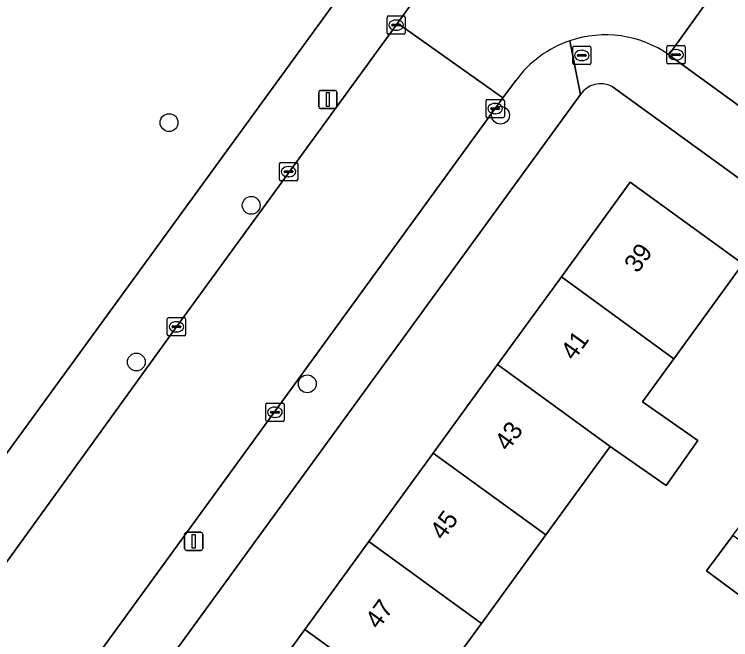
# Model space of a CAD drawing. Extents: x 159674 to 160531, y 382172 to 382904.
# Drawn here: x 160100.56 to 160139.82, y 382591.51 to 382625.81 of the extents above; entities that cross this region are included whole.
import ezdxf

# ---------------------------------------------------------------- set-up
doc = ezdxf.new("R2010")
doc.units = 0
for name, color, linetype in [('IMGEO_Boom', 7, 'Continuous'), ('IMGEO_Brandkraan', 7, 'Continuous'), ('IMGEO_Erf', 7, 'Continuous'), ('IMGEO_Kolk', 7, 'Continuous'), ('IMGEO_Lichtmast', 7, 'Continuous'), ('IMGEO_Pand', 7, 'Continuous'), ('IMGEO_Pand_nummerreeks', 7, 'Continuous'), ('IMGEO_Rijbaan_lokaal_open', 7, 'Continuous'), ('IMGEO_Voetpad_open', 7, 'Continuous')]:
    doc.layers.add(name, color=color, linetype=linetype)

msp = doc.modelspace()

# ---------------------------------------------------------------- linework, layer by layer
at = {"layer": 'IMGEO_Boom'}
for centre in [(160127.205, 382620.272), (160109.04, 382619.867), (160113.544, 382615.329), (160107.245, 382606.738), (160116.616, 382605.543)]:
    msp.add_circle(centre, 0.489, dxfattribs=at)
at = {"layer": 'IMGEO_Brandkraan'}
for p, q in [((160131.163, 382623.125), (160131.163, 382623.977)), ((160131.238, 382624.051), (160132.09, 382624.051)), ((160131.651, 382623.831), (160131.676, 382623.831)), ((160132.164, 382623.977), (160132.164, 382623.125)), ((160131.422, 382623.545), (160131.422, 382623.557)), ((160131.86, 382623.508), (160131.462, 382623.508)), ((160131.465, 382623.594), (160131.863, 382623.594)), ((160131.906, 382623.557), (160131.906, 382623.545)), ((160132.09, 382623.051), (160131.238, 382623.051)), ((160131.674, 382623.271), (160131.649, 382623.271))]:
    msp.add_line(p, q, dxfattribs=at)
for points in [[(160131.163, 382623.125), (160131.163, 382623.977)], [(160131.238, 382624.051), (160132.09, 382624.051)], [(160132.164, 382623.977), (160132.164, 382623.125)], [(160132.09, 382623.051), (160131.238, 382623.051)]]:
    msp.add_lwpolyline(points, dxfattribs=at)
for centre, radius, start, end in [((160131.24, 382623.975), 0.0765, 91.552, 178.448), ((160131.24, 382623.975), 0.0765, 91.552, 178.448), ((160132.088, 382623.975), 0.0765, 1.552, 88.448), ((160132.088, 382623.975), 0.0765, 1.552, 88.448), ((160131.462, 382623.554), 0.0403, 85.8775, 175.7526), ((160131.459, 382623.544), 0.0366, 178.938, 274.7102), ((160131.863, 382623.551), 0.043, 264.8664, 352.4533), ((160131.867, 382623.556), 0.0386, 1.7309, 96.639), ((160131.24, 382623.127), 0.0765, 181.552, 268.448), ((160131.24, 382623.127), 0.0765, 181.552, 268.448), ((160132.088, 382623.127), 0.0765, 271.552, 358.448), ((160132.088, 382623.127), 0.0765, 271.552, 358.448)]:
    msp.add_arc(centre, radius, start, end, dxfattribs=at)
for centre, major_axis, ratio, start_param, end_param in [((160131.65, 382623.551), (-0.387, 0.002), 0.722429, 4.712389, 7.853982), ((160131.675, 382623.551), (-0.39, 0.002), 0.717154, 1.570796, 4.712389)]:
    msp.add_ellipse(centre, major_axis=major_axis, ratio=ratio, start_param=start_param, end_param=end_param, dxfattribs=at)
at = {"layer": 'IMGEO_Erf'}
for points in [[(160078.977, 382572.654), (160139.025, 382655.211), (160118.682, 382670.24), (160112.498, 382662.82), (160085.741, 382648.366)], [(160143.206, 382591.48), (160143.351, 382591.675), (160138.506, 382595.279), (160139.948, 382597.218), (160141.485, 382599.284), (160142.407, 382598.663), (160144.535, 382601.523), (160148.493, 382598.578), (160150.775, 382601.469), (160145.778, 382605.101), (160147.195, 382607.051), (160152.192, 382603.418), (160154.437, 382606.506), (160154.426, 382606.548), (160133.33, 382621.844)], [(160131.588, 382621.403), (160103.888, 382583.337)]]:
    msp.add_lwpolyline(points, dxfattribs=at)
msp.add_lwpolyline([(160133.217, 382602.109), (160129.69, 382597.257), (160126.162, 382592.404), (160124.357, 382589.921), (160126.478, 382588.471), (160124.848, 382586.086), (160122.658, 382587.583), (160125.105, 382585.804), (160121.543, 382580.904), (160119.095, 382582.683), (160115.643, 382577.934), (160109.474, 382582.419), (160112.925, 382587.167), (160116.488, 382592.067), (160119.993, 382596.889), (160123.52, 382601.741), (160127.047, 382606.593), (160130.542, 382611.402), (160134.322, 382616.601), (160140.492, 382612.116), (160136.713, 382606.917), (160134.991, 382604.549), (160138.019, 382602.434), (160136.291, 382599.961)], close=True, dxfattribs=at)
msp.add_arc((160132.7, 382620.672), 1.33, 61.7224, 146.6903, dxfattribs=at)
at = {"layer": 'IMGEO_Kolk'}
for p, q in [((160121.062, 382625.714), (160121.914, 382625.714)), ((160120.987, 382624.788), (160120.987, 382625.64)), ((160121.475, 382625.494), (160121.5, 382625.494)), ((160121.988, 382625.64), (160121.988, 382624.788)), ((160121.246, 382625.208), (160121.246, 382625.22)), ((160121.684, 382625.171), (160121.286, 382625.171)), ((160121.289, 382625.257), (160121.687, 382625.257)), ((160121.498, 382624.934), (160121.473, 382624.934)), ((160121.73, 382625.22), (160121.73, 382625.208)), ((160121.914, 382624.714), (160121.062, 382624.714)), ((160136.327, 382623.163), (160136.327, 382624.015)), ((160136.402, 382624.089), (160137.254, 382624.089)), ((160136.815, 382623.869), (160136.84, 382623.869)), ((160137.328, 382624.015), (160137.328, 382623.163)), ((160136.586, 382623.583), (160136.586, 382623.595)), ((160137.024, 382623.546), (160136.626, 382623.546)), ((160136.629, 382623.632), (160137.027, 382623.632)), ((160137.07, 382623.595), (160137.07, 382623.583)), ((160137.254, 382623.089), (160136.402, 382623.089)), ((160136.838, 382623.309), (160136.813, 382623.309)), ((160126.417, 382620.21), (160126.417, 382621.062)), ((160126.492, 382621.136), (160127.344, 382621.136)), ((160127.418, 382621.062), (160127.418, 382620.21)), ((160126.676, 382620.63), (160126.676, 382620.642)), ((160126.719, 382620.679), (160127.117, 382620.679)), ((160126.905, 382620.916), (160126.93, 382620.916)), ((160127.16, 382620.642), (160127.16, 382620.63)), ((160127.114, 382620.593), (160126.716, 382620.593)), ((160126.928, 382620.356), (160126.903, 382620.356)), ((160127.344, 382620.136), (160126.492, 382620.136)), ((160115.09, 382616.749), (160115.09, 382617.601)), ((160115.165, 382617.675), (160116.017, 382617.675)), ((160116.091, 382617.601), (160116.091, 382616.749)), ((160115.349, 382617.169), (160115.349, 382617.181)), ((160115.787, 382617.132), (160115.389, 382617.132)), ((160115.392, 382617.218), (160115.79, 382617.218)), ((160115.578, 382617.455), (160115.603, 382617.455)), ((160115.833, 382617.181), (160115.833, 382617.169)), ((160116.017, 382616.675), (160115.165, 382616.675)), ((160115.601, 382616.895), (160115.576, 382616.895)), ((160108.942, 382608.244), (160108.942, 382609.096)), ((160109.017, 382609.17), (160109.869, 382609.17)), ((160109.43, 382608.95), (160109.455, 382608.95)), ((160109.943, 382609.096), (160109.943, 382608.244)), ((160109.201, 382608.664), (160109.201, 382608.676)), ((160109.639, 382608.627), (160109.241, 382608.627)), ((160109.244, 382608.713), (160109.642, 382608.713)), ((160109.685, 382608.676), (160109.685, 382608.664)), ((160109.869, 382608.17), (160109.017, 382608.17)), ((160109.453, 382608.39), (160109.428, 382608.39)), ((160114.343, 382603.556), (160114.343, 382604.408)), ((160114.418, 382604.482), (160115.27, 382604.482)), ((160114.831, 382604.262), (160114.856, 382604.262)), ((160115.344, 382604.408), (160115.344, 382603.556)), ((160114.602, 382603.976), (160114.602, 382603.988)), ((160115.04, 382603.939), (160114.642, 382603.939)), ((160114.645, 382604.025), (160115.043, 382604.025)), ((160115.086, 382603.988), (160115.086, 382603.976)), ((160115.27, 382603.482), (160114.418, 382603.482)), ((160114.854, 382603.702), (160114.829, 382603.702))]:
    msp.add_line(p, q, dxfattribs=at)
for points in [[(160121.062, 382625.714), (160121.914, 382625.714)], [(160120.987, 382624.788), (160120.987, 382625.64)], [(160121.988, 382625.64), (160121.988, 382624.788)], [(160121.914, 382624.714), (160121.062, 382624.714)], [(160136.327, 382623.163), (160136.327, 382624.015)], [(160136.402, 382624.089), (160137.254, 382624.089)], [(160137.328, 382624.015), (160137.328, 382623.163)], [(160137.254, 382623.089), (160136.402, 382623.089)], [(160126.417, 382620.21), (160126.417, 382621.062)], [(160126.492, 382621.136), (160127.344, 382621.136)], [(160127.418, 382621.062), (160127.418, 382620.21)], [(160127.344, 382620.136), (160126.492, 382620.136)], [(160115.09, 382616.749), (160115.09, 382617.601)], [(160115.165, 382617.675), (160116.017, 382617.675)], [(160116.091, 382617.601), (160116.091, 382616.749)], [(160116.017, 382616.675), (160115.165, 382616.675)], [(160108.942, 382608.244), (160108.942, 382609.096)], [(160109.017, 382609.17), (160109.869, 382609.17)], [(160109.943, 382609.096), (160109.943, 382608.244)], [(160109.869, 382608.17), (160109.017, 382608.17)], [(160114.343, 382603.556), (160114.343, 382604.408)], [(160114.418, 382604.482), (160115.27, 382604.482)], [(160115.344, 382604.408), (160115.344, 382603.556)], [(160115.27, 382603.482), (160114.418, 382603.482)]]:
    msp.add_lwpolyline(points, dxfattribs=at)
for centre, radius, start, end in [((160121.064, 382625.638), 0.0765, 91.552, 178.448), ((160121.064, 382625.638), 0.0765, 91.552, 178.448), ((160121.912, 382625.638), 0.0765, 1.552, 88.448), ((160121.912, 382625.638), 0.0765, 1.552, 88.448), ((160121.286, 382625.217), 0.0403, 85.8775, 175.7526), ((160121.283, 382625.207), 0.0366, 178.938, 274.7102), ((160121.687, 382625.214), 0.043, 264.8664, 352.4533), ((160121.691, 382625.219), 0.0386, 1.7309, 96.639), ((160121.064, 382624.79), 0.0765, 181.552, 268.448), ((160121.064, 382624.79), 0.0765, 181.552, 268.448), ((160121.912, 382624.79), 0.0765, 271.552, 358.448), ((160121.912, 382624.79), 0.0765, 271.552, 358.448), ((160136.404, 382624.013), 0.0765, 91.552, 178.448), ((160136.404, 382624.013), 0.0765, 91.552, 178.448), ((160137.252, 382624.013), 0.0765, 1.552, 88.448), ((160137.252, 382624.013), 0.0765, 1.552, 88.448), ((160136.626, 382623.592), 0.0403, 85.8775, 175.7526), ((160136.623, 382623.582), 0.0366, 178.938, 274.7102), ((160137.027, 382623.589), 0.043, 264.8664, 352.4533), ((160137.031, 382623.594), 0.0386, 1.7309, 96.639), ((160136.404, 382623.165), 0.0765, 181.552, 268.448), ((160136.404, 382623.165), 0.0765, 181.552, 268.448), ((160137.252, 382623.165), 0.0765, 271.552, 358.448), ((160137.252, 382623.165), 0.0765, 271.552, 358.448), ((160126.494, 382621.06), 0.0765, 91.552, 178.448), ((160126.494, 382621.06), 0.0765, 91.552, 178.448), ((160127.342, 382621.06), 0.0765, 1.552, 88.448), ((160127.342, 382621.06), 0.0765, 1.552, 88.448), ((160126.716, 382620.639), 0.0403, 85.8775, 175.7526), ((160126.713, 382620.629), 0.0366, 178.938, 274.7102), ((160127.117, 382620.636), 0.043, 264.8664, 352.4533), ((160127.121, 382620.641), 0.0386, 1.7309, 96.639), ((160126.494, 382620.212), 0.0765, 181.552, 268.448), ((160126.494, 382620.212), 0.0765, 181.552, 268.448), ((160127.342, 382620.212), 0.0765, 271.552, 358.448), ((160127.342, 382620.212), 0.0765, 271.552, 358.448), ((160115.167, 382617.599), 0.0765, 91.552, 178.448), ((160115.167, 382617.599), 0.0765, 91.552, 178.448), ((160116.015, 382617.599), 0.0765, 1.552, 88.448), ((160116.015, 382617.599), 0.0765, 1.552, 88.448), ((160115.389, 382617.178), 0.0403, 85.8775, 175.7526), ((160115.386, 382617.168), 0.0366, 178.938, 274.7102), ((160115.79, 382617.175), 0.043, 264.8664, 352.4533), ((160115.794, 382617.18), 0.0386, 1.7309, 96.639), ((160115.167, 382616.751), 0.0765, 181.552, 268.448), ((160115.167, 382616.751), 0.0765, 181.552, 268.448), ((160116.015, 382616.751), 0.0765, 271.552, 358.448), ((160116.015, 382616.751), 0.0765, 271.552, 358.448), ((160109.019, 382609.094), 0.0765, 91.552, 178.448), ((160109.019, 382609.094), 0.0765, 91.552, 178.448), ((160109.867, 382609.094), 0.0765, 1.552, 88.448), ((160109.867, 382609.094), 0.0765, 1.552, 88.448), ((160109.241, 382608.673), 0.0403, 85.8775, 175.7526), ((160109.238, 382608.663), 0.0366, 178.938, 274.7102), ((160109.642, 382608.67), 0.043, 264.8664, 352.4533), ((160109.646, 382608.675), 0.0386, 1.7309, 96.639), ((160109.019, 382608.246), 0.0765, 181.552, 268.448), ((160109.019, 382608.246), 0.0765, 181.552, 268.448), ((160109.867, 382608.246), 0.0765, 271.552, 358.448), ((160109.867, 382608.246), 0.0765, 271.552, 358.448), ((160114.42, 382604.406), 0.0765, 91.552, 178.448), ((160114.42, 382604.406), 0.0765, 91.552, 178.448), ((160115.268, 382604.406), 0.0765, 1.552, 88.448), ((160115.268, 382604.406), 0.0765, 1.552, 88.448), ((160114.642, 382603.985), 0.0403, 85.8775, 175.7526), ((160114.639, 382603.975), 0.0366, 178.938, 274.7102), ((160115.043, 382603.982), 0.043, 264.8664, 352.4533), ((160115.047, 382603.987), 0.0386, 1.7309, 96.639), ((160114.42, 382603.558), 0.0765, 181.552, 268.448), ((160114.42, 382603.558), 0.0765, 181.552, 268.448), ((160115.268, 382603.558), 0.0765, 271.552, 358.448), ((160115.268, 382603.558), 0.0765, 271.552, 358.448)]:
    msp.add_arc(centre, radius, start, end, dxfattribs=at)
for centre, major_axis, ratio, start_param, end_param in [((160121.474, 382625.214), (-0.387, 0.002), 0.722429, 4.712389, 7.853982), ((160121.499, 382625.214), (-0.39, 0.002), 0.717154, 1.570796, 4.712389), ((160136.814, 382623.589), (-0.387, 0.002), 0.722429, 4.712389, 7.853982), ((160136.839, 382623.589), (-0.39, 0.002), 0.717154, 1.570796, 4.712389), ((160126.904, 382620.636), (-0.387, 0.002), 0.722429, 4.712389, 7.853982), ((160126.929, 382620.636), (-0.39, 0.002), 0.717154, 1.570796, 4.712389), ((160115.577, 382617.175), (-0.387, 0.002), 0.722429, 4.712389, 7.853982), ((160115.602, 382617.175), (-0.39, 0.002), 0.717154, 1.570796, 4.712389), ((160109.429, 382608.67), (-0.387, 0.002), 0.722429, 4.712389, 7.853982), ((160109.454, 382608.67), (-0.39, 0.002), 0.717154, 1.570796, 4.712389), ((160114.83, 382603.982), (-0.387, 0.002), 0.722429, 4.712389, 7.853982), ((160114.855, 382603.982), (-0.39, 0.002), 0.717154, 1.570796, 4.712389)]:
    msp.add_ellipse(centre, major_axis=major_axis, ratio=ratio, start_param=start_param, end_param=end_param, dxfattribs=at)
at = {"layer": 'IMGEO_Lichtmast'}
for p, q in [((160117.246, 382620.734), (160117.246, 382621.534)), ((160117.246, 382621.534), (160117.246, 382620.734)), ((160117.346, 382621.634), (160118.136, 382621.634)), ((160118.136, 382621.634), (160117.346, 382621.634)), ((160118.236, 382621.534), (160118.236, 382620.734)), ((160118.236, 382620.734), (160118.236, 382621.534)), ((160118.136, 382620.634), (160117.346, 382620.634)), ((160117.346, 382620.634), (160118.136, 382620.634)), ((160109.893, 382596.504), (160109.893, 382597.304)), ((160109.893, 382597.304), (160109.893, 382596.504)), ((160109.993, 382597.404), (160110.783, 382597.404)), ((160110.783, 382597.404), (160109.993, 382597.404)), ((160110.883, 382597.304), (160110.883, 382596.504)), ((160110.883, 382596.504), (160110.883, 382597.304)), ((160110.783, 382596.404), (160109.993, 382596.404)), ((160109.993, 382596.404), (160110.783, 382596.404))]:
    msp.add_line(p, q, dxfattribs=at)
for points in [[(160117.666, 382621.509), (160117.816, 382621.509), (160117.816, 382620.759), (160117.666, 382620.759), (160117.666, 382621.509)], [(160110.313, 382597.279), (160110.463, 382597.279), (160110.463, 382596.529), (160110.313, 382596.529), (160110.313, 382597.279)]]:
    msp.add_lwpolyline(points, dxfattribs=at)
for centre, start, end in [((160117.346, 382621.534), 90, 180), ((160117.346, 382621.534), 90, 180), ((160118.136, 382621.534), 0, 90), ((160118.136, 382621.534), 360, 90), ((160117.346, 382620.734), 180, 270), ((160117.346, 382620.734), 180, 270), ((160118.136, 382620.734), 270, 0), ((160118.136, 382620.734), 270, 0), ((160109.993, 382597.304), 90, 180), ((160109.993, 382597.304), 90, 180), ((160110.783, 382597.304), 0, 90), ((160110.783, 382597.304), 360, 90), ((160109.993, 382596.504), 180, 270), ((160109.993, 382596.504), 180, 270), ((160110.783, 382596.504), 270, 0), ((160110.783, 382596.504), 270, 0)]:
    msp.add_arc(centre, 0.1, start, end, dxfattribs=at)
at = {"layer": 'IMGEO_Pand'}
for points in [[(160130.542, 382611.402), (160136.713, 382606.917), (160140.492, 382612.116), (160134.322, 382616.601)], [(160133.217, 382602.109), (160136.291, 382599.961), (160138.019, 382602.434), (160134.991, 382604.549), (160136.713, 382606.917), (160130.542, 382611.402), (160127.047, 382606.593)], [(160133.217, 382602.109), (160127.047, 382606.593), (160123.52, 382601.741), (160129.69, 382597.257)], [(160126.162, 382592.404), (160129.69, 382597.257), (160123.52, 382601.741), (160119.993, 382596.889)], [(160139.948, 382597.218), (160138.506, 382595.279), (160143.351, 382591.675), (160143.536, 382591.538), (160145.02, 382593.532), (160144.833, 382593.668)], [(160119.993, 382596.889), (160116.488, 382592.067), (160122.658, 382587.583), (160124.848, 382586.086), (160126.478, 382588.471), (160124.357, 382589.921), (160126.162, 382592.404)], [(160122.658, 382587.583), (160116.488, 382592.067), (160112.925, 382587.167), (160119.095, 382582.683), (160121.543, 382580.904), (160125.105, 382585.804)]]:
    msp.add_lwpolyline(points, close=True, dxfattribs=at)
at = {"layer": 'IMGEO_Rijbaan_lokaal_open'}
for points in [[(160139.276, 382637.61), (160139.698, 382638.176), (160133.916, 382642.352), (160121.569, 382625.329), (160127.333, 382621.232), (160128.048, 382622.176)], [(160136.439, 382623.587), (160140.555, 382629.351)], [(160140.763, 382629.192), (160140.555, 382629.351), (160136.439, 382623.587), (160136.712, 382623.379), (160240.412, 382548.029)], [(160102.443, 382586.988), (160126.918, 382620.636), (160127.333, 382621.232), (160121.569, 382625.329), (160121.488, 382625.214), (160109.443, 382608.67), (160097.463, 382592.089), (160084.229, 382573.928), (160076.311, 382563.035), (160076.064, 382562.694), (160071.89, 382556.928), (160067.829, 382551.317), (160067.089, 382550.301), (160063.381, 382545.206), (160061.047, 382541.977), (160060.192, 382540.757), (160059.002, 382539.131), (160063.104, 382536.111)]]:
    msp.add_lwpolyline(points, dxfattribs=at)
for centre, radius, start, end in [((160132.963, 382618.596), 6.082, 55.148, 108.7542), ((160132.956, 382618.609), 6.068, 108.7276, 143.9896)]:
    msp.add_arc(centre, radius, start, end, dxfattribs=at)
at = {"layer": 'IMGEO_Voetpad_open'}
for points in [[(160160.682, 382684.114), (160158.819, 382681.732), (160139.364, 382654.969), (160139.025, 382655.211), (160078.977, 382572.654), (160073.24, 382564.766), (160076.064, 382562.694), (160076.311, 382563.035), (160084.229, 382573.928), (160097.463, 382592.089), (160109.443, 382608.67), (160121.488, 382625.214), (160121.569, 382625.329), (160133.916, 382642.352), (160134.723, 382643.445), (160146.792, 382660.104), (160161.775, 382680.602)], [(160131.588, 382621.403), (160131.008, 382624.355)], [(160131.008, 382624.355), (160131.588, 382621.403)], [(160136.712, 382623.379), (160136.439, 382623.587)], [(160240.412, 382548.029), (160136.712, 382623.379)], [(160128.048, 382622.176), (160127.333, 382621.232), (160126.918, 382620.636), (160102.443, 382586.988)], [(160133.33, 382621.844), (160154.426, 382606.548), (160154.437, 382606.506), (160154.946, 382604.626)], [(160100.791, 382582.263), (160103.888, 382583.337), (160131.588, 382621.403)]]:
    msp.add_lwpolyline(points, dxfattribs=at)
for centre, radius, start, end in [((160132.963, 382618.596), 6.082, 55.148, 108.7542), ((160132.956, 382618.609), 6.068, 108.7276, 143.9896), ((160132.7, 382620.672), 1.33, 61.7224, 146.6903)]:
    msp.add_arc(centre, radius, start, end, dxfattribs=at)

# ---------------------------------------------------------------- texts
at = {"layer": 'IMGEO_Pand_nummerreeks'}
for s, p in [('39', (160134.715, 382611.562)), ('41', (160131.231, 382606.77)), ('43', (160127.615, 382601.796)), ('45', (160124.066, 382596.913)), ('47', (160120.516, 382592.03))]:
    msp.add_text(s, height=1, rotation=53.9854, dxfattribs=at).set_placement(p)

doc.saveas('drawing.dxf')
